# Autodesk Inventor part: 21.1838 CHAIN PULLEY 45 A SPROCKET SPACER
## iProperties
Created: 2007-05
Part Number: 21.1838 CHAIN PULLEY 45 A SPROCKET SPACER
Material: Steel
Document SubType Name: Modeling
Designer: Andy Moles
Mass: 6.65861 g
Surface Area: 7.35133 cm^2
Volume: 0.84823 cm^3
Density: 7.85 g/cm^3
Author: Andy Moles
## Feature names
1. Extrusion1
